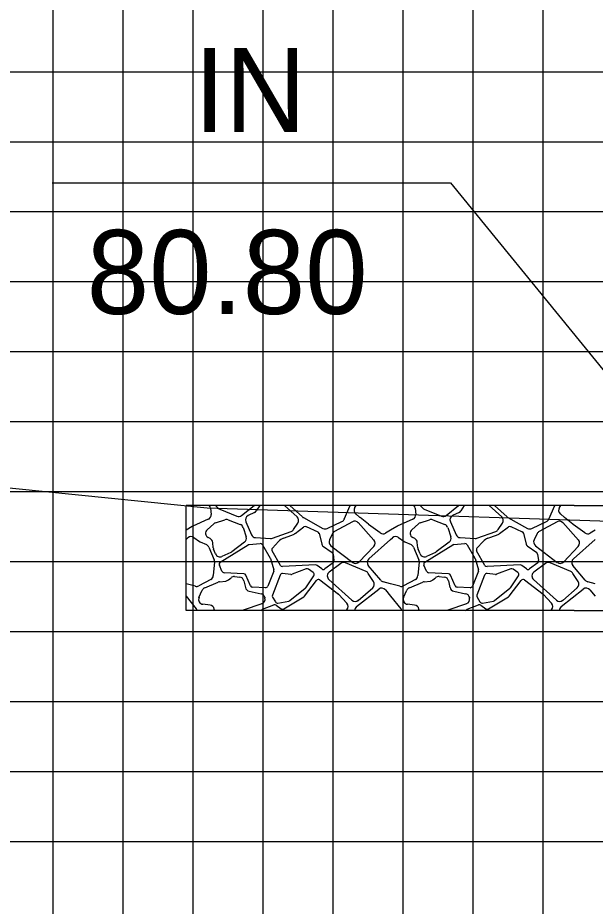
# Model space of a CAD drawing. Extents: x 857504 to 857847, y 364765 to 364985.
# Drawn here: x 857586.8 to 857595.05, y 364923.38 to 364936.07 of the extents above; entities that cross this region are included whole.
import ezdxf

# ---------------------------------------------------------------- set-up
doc = ezdxf.new("R2010")
doc.units = 0
for name, color, linetype in [('ANNOTATION', 7, 'Continuous'), ('D_Roadway_SlopeLines', 7, 'Continuous'), ('MAJOR', 7, 'Continuous'), ('MINOR', 7, 'Continuous'), ('S_Roadway_Centerline', 7, 'Continuous')]:
    doc.layers.add(name, color=color, linetype=linetype)

msp = doc.modelspace()

# ---------------------------------------------------------------- linework, layer by layer
at = {"layer": 'ANNOTATION'}
msp.add_lwpolyline([(857587.292, 364933.714), (857592.983, 364933.714), (857596.751, 364929.101)], dxfattribs=at)
at = {"layer": 'D_Roadway_SlopeLines'}
for p, q in [((857594.751, 364929.101), (857589.205, 364929.101)), ((857589.555, 364929.066), (857589.564, 364928.975)), ((857589.628, 364929.101), (857589.664, 364929.064)), ((857589.687, 364929.049), (857589.931, 364928.949)), ((857590, 364928.959), (857590.178, 364929.101)), ((857590.259, 364929.101), (857590.209, 364929.028)), ((857590.792, 364928.943), (857590.611, 364929.101)), ((857590.688, 364929.101), (857590.87, 364928.939)), ((857591.467, 364928.909), (857591.55, 364929.101)), ((857591.62, 364929.077), (857591.638, 364929.101)), ((857592.48, 364929.066), (857592.488, 364928.975)), ((857592.552, 364929.101), (857592.589, 364929.064)), ((857592.611, 364929.049), (857592.856, 364928.949)), ((857592.925, 364928.959), (857593.102, 364929.101)), ((857593.183, 364929.101), (857593.134, 364929.028)), ((857593.717, 364928.943), (857593.536, 364929.101)), ((857593.613, 364929.101), (857593.794, 364928.939)), ((857594.392, 364928.909), (857594.475, 364929.101)), ((857594.545, 364929.077), (857594.563, 364929.101)), ((857594.751, 364929.101), (857596.751, 364929.101)), ((857589.523, 364928.906), (857589.3, 364928.807)), ((857589.626, 364928.855), (857589.76, 364928.899)), ((857589.806, 364928.898), (857589.98, 364928.832)), ((857590.183, 364929.005), (857590.091, 364928.959)), ((857590.882, 364928.93), (857591.162, 364928.776)), ((857591.691, 364928.934), (857591.631, 364928.982)), ((857591.811, 364928.836), (857591.692, 364928.933)), ((857592.448, 364928.906), (857592.224, 364928.807)), ((857592.551, 364928.855), (857592.685, 364928.899)), ((857592.731, 364928.898), (857592.905, 364928.832)), ((857593.108, 364929.005), (857593.016, 364928.959)), ((857593.807, 364928.93), (857594.087, 364928.776)), ((857594.616, 364928.934), (857594.556, 364928.982)), ((857594.736, 364928.836), (857594.617, 364928.933)), ((857589.293, 364928.803), (857589.205, 364928.751)), ((857589.507, 364928.757), (857589.603, 364928.841)), ((857590.02, 364928.79), (857590.066, 364928.655)), ((857590.059, 364928.87), (857590.141, 364928.685)), ((857590.741, 364928.759), (857590.804, 364928.853)), ((857590.763, 364928.702), (857590.89, 364928.797)), ((857590.924, 364928.801), (857591.087, 364928.729)), ((857591.224, 364928.775), (857591.434, 364928.874)), ((857591.584, 364928.872), (857591.329, 364928.732)), ((857591.889, 364928.61), (857591.667, 364928.858)), ((857591.98, 364928.711), (857591.814, 364928.834)), ((857592.217, 364928.803), (857592.13, 364928.751)), ((857592.432, 364928.757), (857592.528, 364928.841)), ((857592.945, 364928.79), (857592.991, 364928.655)), ((857592.984, 364928.87), (857593.065, 364928.685)), ((857593.665, 364928.759), (857593.729, 364928.853)), ((857593.687, 364928.702), (857593.814, 364928.797)), ((857593.849, 364928.801), (857594.012, 364928.729)), ((857594.149, 364928.775), (857594.359, 364928.874)), ((857594.508, 364928.872), (857594.253, 364928.732)), ((857594.814, 364928.61), (857594.592, 364928.858)), ((857594.905, 364928.711), (857594.739, 364928.834)), ((857589.205, 364928.617), (857589.233, 364928.641)), ((857589.317, 364928.645), (857589.396, 364928.59)), ((857589.55, 364928.63), (857589.52, 364928.645)), ((857590.199, 364928.644), (857590.412, 364928.632)), ((857590.439, 364928.636), (857590.707, 364928.733)), ((857590.597, 364928.636), (857590.716, 364928.677)), ((857591.106, 364928.706), (857591.145, 364928.549)), ((857591.3, 364928.703), (857591.256, 364928.614)), ((857592.13, 364928.751), (857592.056, 364928.707)), ((857592.13, 364928.617), (857592.157, 364928.641)), ((857592.242, 364928.645), (857592.321, 364928.59)), ((857592.475, 364928.63), (857592.445, 364928.645)), ((857593.124, 364928.644), (857593.337, 364928.632)), ((857593.364, 364928.636), (857593.632, 364928.733)), ((857593.521, 364928.636), (857593.641, 364928.677)), ((857594.031, 364928.706), (857594.069, 364928.549)), ((857594.225, 364928.703), (857594.181, 364928.614)), ((857595.054, 364928.751), (857594.98, 364928.707)), ((857589.408, 364928.583), (857589.497, 364928.544)), ((857589.533, 364928.508), (857589.607, 364928.329)), ((857589.594, 364928.499), (857589.587, 364928.575)), ((857589.695, 364928.295), (857590.094, 364928.54)), ((857590.042, 364928.579), (857589.858, 364928.439)), ((857590.109, 364928.545), (857590.265, 364928.558)), ((857590.297, 364928.541), (857590.409, 364928.351)), ((857590.439, 364928.495), (857590.527, 364928.59)), ((857591.158, 364928.529), (857591.293, 364928.43)), ((857591.276, 364928.529), (857591.588, 364928.291)), ((857591.679, 364928.298), (857591.888, 364928.518)), ((857591.817, 364928.343), (857592.13, 364928.617)), ((857592.333, 364928.583), (857592.422, 364928.544)), ((857592.458, 364928.508), (857592.532, 364928.329)), ((857592.518, 364928.499), (857592.511, 364928.575)), ((857592.62, 364928.295), (857593.019, 364928.54)), ((857592.967, 364928.579), (857592.782, 364928.439)), ((857593.034, 364928.545), (857593.189, 364928.558)), ((857593.222, 364928.541), (857593.333, 364928.351)), ((857593.364, 364928.495), (857593.452, 364928.59)), ((857594.082, 364928.529), (857594.218, 364928.43)), ((857594.2, 364928.529), (857594.512, 364928.291)), ((857594.603, 364928.298), (857594.812, 364928.518)), ((857594.742, 364928.343), (857595.054, 364928.617)), ((857589.628, 364928.411), (857589.599, 364928.478)), ((857589.844, 364928.432), (857589.718, 364928.376)), ((857590.553, 364928.247), (857590.434, 364928.455)), ((857591.306, 364928.408), (857591.32, 364928.319)), ((857592.552, 364928.411), (857592.524, 364928.478)), ((857592.769, 364928.432), (857592.643, 364928.376)), ((857593.478, 364928.247), (857593.359, 364928.455)), ((857594.231, 364928.408), (857594.245, 364928.319)), ((857589.612, 364928.297), (857589.594, 364928.101)), ((857589.719, 364928.164), (857589.681, 364928.253)), ((857590.412, 364928.344), (857590.46, 364928.185)), ((857591.057, 364928.255), (857590.585, 364928.23)), ((857591.307, 364928.286), (857591.189, 364928.196)), ((857591.418, 364928.275), (857591.252, 364928.152)), ((857591.78, 364928.159), (857591.486, 364928.283)), ((857592.537, 364928.297), (857592.519, 364928.101)), ((857592.643, 364928.164), (857592.606, 364928.253)), ((857593.337, 364928.344), (857593.385, 364928.185)), ((857593.982, 364928.255), (857593.509, 364928.23)), ((857594.232, 364928.286), (857594.114, 364928.196)), ((857594.343, 364928.275), (857594.177, 364928.152)), ((857594.704, 364928.159), (857594.411, 364928.283)), ((857590.031, 364928.126), (857589.748, 364928.143)), ((857590.459, 364928.163), (857590.374, 364927.951)), ((857590.705, 364928.118), (857590.584, 364928.13)), ((857590.923, 364928.196), (857590.72, 364928.12)), ((857591.021, 364928.148), (857590.954, 364928.192)), ((857591.147, 364928.196), (857591.08, 364928.248)), ((857591.988, 364928.036), (857591.81, 364928.247)), ((857591.885, 364928.018), (857591.81, 364928.133)), ((857592.956, 364928.126), (857592.673, 364928.143)), ((857593.384, 364928.163), (857593.299, 364927.951)), ((857593.63, 364928.118), (857593.509, 364928.13)), ((857593.848, 364928.196), (857593.645, 364928.12)), ((857593.946, 364928.148), (857593.879, 364928.192)), ((857594.072, 364928.196), (857594.005, 364928.248)), ((857594.912, 364928.036), (857594.735, 364928.247)), ((857594.81, 364928.018), (857594.735, 364928.133)), ((857589.558, 364928.047), (857589.388, 364927.956)), ((857589.472, 364927.928), (857589.665, 364928.008)), ((857589.683, 364928.013), (857589.775, 364928.024)), ((857589.81, 364928.04), (857589.848, 364928.072)), ((857589.899, 364928.088), (857589.972, 364928.081)), ((857590.032, 364928.027), (857590.054, 364927.93)), ((857590.126, 364927.956), (857590.06, 364928.106)), ((857590.549, 364928.108), (857590.439, 364927.823)), ((857590.898, 364927.809), (857591.07, 364928.033)), ((857590.916, 364927.929), (857591.03, 364928.1)), ((857591.118, 364928.04), (857591.384, 364927.836)), ((857591.247, 364928.046), (857591.576, 364927.749)), ((857592.13, 364927.985), (857592.023, 364928.014)), ((857592.483, 364928.047), (857592.312, 364927.956)), ((857592.397, 364927.928), (857592.59, 364928.008)), ((857592.608, 364928.013), (857592.699, 364928.024)), ((857592.735, 364928.04), (857592.773, 364928.072)), ((857592.824, 364928.088), (857592.897, 364928.081)), ((857592.957, 364928.027), (857592.978, 364927.93)), ((857593.051, 364927.956), (857592.985, 364928.106)), ((857593.473, 364928.108), (857593.364, 364927.823)), ((857593.823, 364927.809), (857593.995, 364928.033)), ((857593.841, 364927.929), (857593.955, 364928.1)), ((857594.043, 364928.04), (857594.309, 364927.836)), ((857594.172, 364928.046), (857594.501, 364927.749)), ((857595.054, 364927.985), (857594.947, 364928.014)), ((857589.338, 364927.95), (857589.205, 364927.985)), ((857589.39, 364927.787), (857589.436, 364927.892)), ((857590.107, 364927.878), (857590.277, 364927.843)), ((857590.341, 364927.929), (857590.156, 364927.935)), ((857590.69, 364927.745), (857590.909, 364927.921)), ((857591.644, 364927.658), (857591.959, 364927.907)), ((857591.667, 364927.748), (857591.873, 364927.929)), ((857592.054, 364927.897), (857592.13, 364927.806)), ((857592.263, 364927.95), (857592.13, 364927.985)), ((857592.315, 364927.787), (857592.361, 364927.892)), ((857593.031, 364927.878), (857593.202, 364927.843)), ((857593.266, 364927.929), (857593.081, 364927.935)), ((857593.614, 364927.745), (857593.834, 364927.921)), ((857594.568, 364927.658), (857594.884, 364927.907)), ((857594.591, 364927.748), (857594.797, 364927.929)), ((857594.979, 364927.897), (857595.054, 364927.806)), ((857589.205, 364927.806), (857589.351, 364927.628)), ((857590.33, 364927.791), (857590.333, 364927.78)), ((857590.442, 364927.793), (857590.482, 364927.726)), ((857590.604, 364927.627), (857590.889, 364927.8)), ((857591.389, 364927.832), (857591.504, 364927.707)), ((857592.13, 364927.806), (857592.276, 364927.628)), ((857593.255, 364927.791), (857593.257, 364927.78)), ((857593.366, 364927.793), (857593.406, 364927.726)), ((857593.528, 364927.627), (857593.814, 364927.8)), ((857594.313, 364927.832), (857594.429, 364927.707)), ((857589.548, 364927.681), (857589.446, 364927.692)), ((857589.609, 364927.616), (857589.609, 364927.621)), ((857590.289, 364927.7), (857590.021, 364927.606)), ((857590.299, 364927.621), (857590.461, 364927.684)), ((857590.494, 364927.68), (857590.566, 364927.628)), ((857590.517, 364927.71), (857590.674, 364927.738)), ((857592.473, 364927.681), (857592.37, 364927.692)), ((857592.534, 364927.616), (857592.533, 364927.621)), ((857593.213, 364927.7), (857592.946, 364927.606)), ((857593.224, 364927.621), (857593.386, 364927.684)), ((857593.418, 364927.68), (857593.491, 364927.628)), ((857593.442, 364927.71), (857593.599, 364927.738)), ((857590.274, 364927.601), (857590.289, 364927.614)), ((857591.504, 364927.614), (857591.491, 364927.601)), ((857593.199, 364927.601), (857593.214, 364927.614)), ((857594.428, 364927.614), (857594.416, 364927.601)), ((857594.751, 364927.601), (857596.751, 364927.601))]:
    msp.add_line(p, q, dxfattribs=at)
msp.add_lwpolyline([(857594.751, 364927.601), (857589.205, 364927.601), (857589.205, 364929.101)], dxfattribs=at)
for centre, radius, start, end in [((857589.487, 364929.06), 0.0684, 5.1944, 36.5817), ((857589.713, 364929.112), 0.0684, 225, 247.6938), ((857590.153, 364929.066), 0.0684, 296.5651, 325.7843), ((857591.674, 364929.035), 0.0684, 141.953, 231.3402), ((857592.412, 364929.06), 0.0684, 5.1944, 36.5817), ((857592.637, 364929.112), 0.0684, 225, 247.6938), ((857593.077, 364929.066), 0.0684, 296.5651, 325.7843), ((857594.599, 364929.035), 0.0684, 141.953, 231.3402), ((857589.496, 364928.969), 0.0684, 293.9625, 5.1944), ((857589.782, 364928.834), 0.0684, 69.0265, 108.4349), ((857589.957, 364929.012), 0.0684, 247.6938, 308.6598), ((857590.122, 364928.898), 0.0684, 116.5651, 203.7495), ((857590.747, 364928.891), 0.0684, 326.0035, 48.8937), ((857590.915, 364928.99), 0.0684, 228.2412, 241.294), ((857591.405, 364928.936), 0.0684, 295.4039, 336.6444), ((857591.649, 364928.88), 0.0684, 50.9061, 51.3402), ((857592.42, 364928.969), 0.0684, 293.9625, 5.1944), ((857592.707, 364928.834), 0.0684, 69.0265, 108.4349), ((857592.882, 364929.012), 0.0684, 247.6938, 308.6598), ((857593.046, 364928.898), 0.0684, 116.5651, 203.7495), ((857593.672, 364928.891), 0.0684, 326.0035, 48.8937), ((857593.84, 364928.99), 0.0684, 228.2412, 241.294), ((857594.329, 364928.936), 0.0684, 295.4039, 336.6444), ((857594.573, 364928.88), 0.0684, 50.9061, 51.3402), ((857589.327, 364928.744), 0.0684, 113.9625, 120.6507), ((857589.648, 364928.79), 0.0684, 108.4349, 131.1859), ((857589.956, 364928.768), 0.0684, 18.7413, 69.0265), ((857590.684, 364928.797), 0.0684, 289.9256, 326.0035), ((857590.91, 364928.769), 0.0342, 66.1398, 126.7644), ((857591.195, 364928.836), 0.0684, 241.294, 295.4039), ((857591.616, 364928.812), 0.0684, 41.8334, 118.7575), ((857591.855, 364928.889), 0.0684, 230.9061, 233.4711), ((857592.252, 364928.744), 0.0684, 113.9625, 120.6507), ((857592.573, 364928.79), 0.0684, 108.4349, 131.1859), ((857592.88, 364928.768), 0.0684, 18.7413, 69.0265), ((857593.609, 364928.797), 0.0684, 289.9256, 326.0035), ((857593.835, 364928.769), 0.0342, 66.1398, 126.7644), ((857594.12, 364928.836), 0.0684, 241.294, 295.4039), ((857594.541, 364928.812), 0.0684, 41.8334, 118.7575), ((857594.779, 364928.889), 0.0684, 230.9061, 233.4711), ((857589.278, 364928.59), 0.0684, 54.7824, 131.257), ((857589.552, 364928.706), 0.0684, 131.1859, 242.3005), ((857590.001, 364928.633), 0.0684, 307.0199, 18.7413), ((857590.203, 364928.712), 0.0684, 203.7495, 266.7755), ((857590.416, 364928.7), 0.0684, 266.7755, 289.9256), ((857590.653, 364928.474), 0.171, 109.1336, 137.3215), ((857590.66, 364928.839), 0.171, 289.1336, 306.7644), ((857591.073, 364928.697), 0.0342, 13.7608, 66.1398), ((857591.361, 364928.672), 0.0684, 118.7575, 153.4931), ((857592.021, 364928.766), 0.0684, 233.4711, 300.6507), ((857592.203, 364928.59), 0.0684, 54.7824, 131.257), ((857592.477, 364928.706), 0.0684, 131.1859, 242.3005), ((857592.926, 364928.633), 0.0684, 307.0199, 18.7413), ((857593.128, 364928.712), 0.0684, 203.7495, 266.7755), ((857593.34, 364928.7), 0.0684, 266.7755, 289.9256), ((857593.577, 364928.474), 0.171, 109.1336, 137.3215), ((857593.585, 364928.839), 0.171, 289.1336, 306.7644), ((857593.998, 364928.697), 0.0342, 13.7608, 66.1398), ((857594.286, 364928.672), 0.0684, 118.7575, 153.4931), ((857594.946, 364928.766), 0.0684, 233.4711, 300.6507), ((857589.436, 364928.646), 0.0684, 234.7824, 246.3706), ((857589.47, 364928.481), 0.0684, 22.4794, 66.3706), ((857589.518, 364928.569), 0.0684, 5.1944, 62.3005), ((857590.112, 364928.511), 0.0342, 94.6669, 121.5514), ((857590.267, 364928.524), 0.0342, 30.5102, 94.6669), ((857591.178, 364928.557), 0.0342, 193.7608, 233.6864), ((857591.317, 364928.583), 0.0684, 153.4931, 232.6367), ((857591.838, 364928.565), 0.0684, 316.4321, 41.8334), ((857592.36, 364928.646), 0.0684, 234.7824, 246.3706), ((857592.395, 364928.481), 0.0684, 22.4794, 66.3706), ((857592.443, 364928.569), 0.0684, 5.1944, 62.3005), ((857593.036, 364928.511), 0.0342, 94.6669, 121.5514), ((857593.192, 364928.524), 0.0342, 30.5102, 94.6669), ((857594.102, 364928.557), 0.0342, 193.7608, 233.6864), ((857594.242, 364928.583), 0.0684, 153.4931, 232.6367), ((857594.763, 364928.565), 0.0684, 316.4321, 41.8334), ((857589.662, 364928.505), 0.0684, 185.1944, 203.3852), ((857589.69, 364928.438), 0.0684, 203.3852, 293.8602), ((857589.817, 364928.494), 0.0684, 293.8602, 307.0199), ((857590.464, 364928.472), 0.0342, 137.3215, 209.792), ((857591.273, 364928.402), 0.0342, 8.7462, 53.6864), ((857592.586, 364928.505), 0.0684, 185.1944, 203.3852), ((857592.615, 364928.438), 0.0684, 203.3852, 293.8602), ((857592.741, 364928.494), 0.0684, 293.8602, 307.0199), ((857593.389, 364928.472), 0.0342, 137.3215, 209.792), ((857594.197, 364928.402), 0.0342, 8.7462, 53.6864), ((857589.544, 364928.303), 0.0684, 354.8056, 22.4794), ((857589.713, 364928.266), 0.0342, 121.5514, 202.6199), ((857590.379, 364928.334), 0.0342, 16.9275, 30.5102), ((857591.059, 364928.22), 0.0342, 52.4314, 92.9903), ((857591.286, 364928.313), 0.0342, 307.5348, 8.7462), ((857591.459, 364928.22), 0.0684, 66.9778, 126.6071), ((857591.629, 364928.345), 0.0684, 232.6367, 316.4321), ((857591.863, 364928.291), 0.0684, 131.257, 219.9575), ((857592.468, 364928.303), 0.0684, 354.8056, 22.4794), ((857592.638, 364928.266), 0.0342, 121.5514, 202.6199), ((857593.304, 364928.334), 0.0342, 16.9275, 30.5102), ((857593.984, 364928.22), 0.0342, 52.4314, 92.9903), ((857594.211, 364928.313), 0.0342, 307.5348, 8.7462), ((857594.384, 364928.22), 0.0684, 66.9778, 126.6071), ((857594.554, 364928.345), 0.0684, 232.6367, 316.4321), ((857594.787, 364928.291), 0.0684, 131.257, 219.9575), ((857589.75, 364928.177), 0.0342, 202.6199, 266.6726), ((857590.029, 364928.092), 0.0342, 23.7495, 86.6726), ((857590.427, 364928.176), 0.0342, 338.1986, 16.9275), ((857590.581, 364928.096), 0.0342, 84.4278, 159.0071), ((857590.583, 364928.264), 0.0342, 209.792, 272.9903), ((857590.935, 364928.164), 0.0342, 56.3099, 110.4835), ((857591.002, 364928.119), 0.0342, 326.3099, 56.3099), ((857591.168, 364928.223), 0.0342, 232.4314, 307.5348), ((857591.293, 364928.097), 0.0684, 126.6071, 227.8776), ((857591.753, 364928.096), 0.0684, 32.9625, 66.9778), ((857592.675, 364928.177), 0.0342, 202.6199, 266.6726), ((857592.954, 364928.092), 0.0342, 23.7495, 86.6726), ((857593.352, 364928.176), 0.0342, 338.1986, 16.9275), ((857593.505, 364928.096), 0.0342, 84.4278, 159.0071), ((857593.508, 364928.264), 0.0342, 209.792, 272.9903), ((857593.86, 364928.164), 0.0342, 56.3099, 110.4835), ((857593.927, 364928.119), 0.0342, 326.3099, 56.3099), ((857594.093, 364928.223), 0.0342, 232.4314, 307.5348), ((857594.218, 364928.097), 0.0684, 126.6071, 227.8776), ((857594.678, 364928.096), 0.0684, 32.9625, 66.9778), ((857589.526, 364928.107), 0.0684, 298.0725, 354.8056), ((857589.692, 364927.945), 0.0684, 97.125, 112.6199), ((857589.766, 364928.092), 0.0684, 277.125, 310.3645), ((857589.892, 364928.02), 0.0684, 84.2894, 130.3645), ((857589.965, 364928.013), 0.0684, 12.4074, 84.2894), ((857590.708, 364928.152), 0.0342, 264.4278, 290.4835), ((857591.097, 364928.013), 0.0342, 52.5946, 142.5946), ((857591.828, 364927.98), 0.0684, 311.2462, 32.9625), ((857592.04, 364928.08), 0.0684, 219.9575, 255.2564), ((857592.451, 364928.107), 0.0684, 298.0725, 354.8056), ((857592.616, 364927.945), 0.0684, 97.125, 112.6199), ((857592.691, 364928.092), 0.0684, 277.125, 310.3645), ((857592.817, 364928.02), 0.0684, 84.2894, 130.3645), ((857592.89, 364928.013), 0.0684, 12.4074, 84.2894), ((857593.633, 364928.152), 0.0342, 264.4278, 290.4835), ((857594.022, 364928.013), 0.0342, 52.5946, 142.5946), ((857594.752, 364927.98), 0.0684, 311.2462, 32.9625), ((857594.965, 364928.08), 0.0684, 219.9575, 255.2564), ((857589.355, 364928.016), 0.0684, 255.2564, 298.0725), ((857589.499, 364927.864), 0.0684, 112.6199, 156.3179), ((857590.12, 364927.945), 0.0684, 192.4074, 258.3664), ((857590.157, 364927.969), 0.0342, 203.7495, 268.1221), ((857590.343, 364927.963), 0.0342, 268.1221, 338.1986), ((857590.888, 364927.948), 0.0342, 308.7742, 326.3099), ((857592.002, 364927.854), 0.0684, 39.4712, 128.373), ((857592.28, 364928.016), 0.0684, 255.2564, 298.0725), ((857592.423, 364927.864), 0.0684, 112.6199, 156.3179), ((857593.045, 364927.945), 0.0684, 192.4074, 258.3664), ((857593.082, 364927.969), 0.0342, 203.7495, 268.1221), ((857593.267, 364927.963), 0.0342, 268.1221, 338.1986), ((857593.812, 364927.948), 0.0342, 308.7742, 326.3099), ((857594.926, 364927.854), 0.0684, 39.4712, 128.373), ((857589.453, 364927.76), 0.0684, 156.3179, 263.9458), ((857590.263, 364927.776), 0.0684, 13.134, 78.3664), ((857590.266, 364927.765), 0.0684, 289.406, 13.134), ((857590.471, 364927.811), 0.0342, 159.0071, 210.6507), ((857590.668, 364927.772), 0.0342, 280.204, 308.7742), ((857590.871, 364927.83), 0.0342, 301.373, 322.5946), ((857591.364, 364927.809), 0.0342, 42.7891, 52.5946), ((857591.622, 364927.8), 0.0684, 227.8776, 311.2462), ((857592.378, 364927.76), 0.0684, 156.3179, 263.9458), ((857593.188, 364927.776), 0.0684, 13.134, 78.3664), ((857593.191, 364927.765), 0.0684, 289.406, 13.134), ((857593.396, 364927.811), 0.0342, 159.0071, 210.6507), ((857593.593, 364927.772), 0.0342, 280.204, 308.7742), ((857593.796, 364927.83), 0.0342, 301.373, 322.5946), ((857594.288, 364927.809), 0.0342, 42.7891, 52.5946), ((857594.546, 364927.8), 0.0684, 227.8776, 311.2462), ((857589.298, 364927.585), 0.0684, 13.3808, 39.4712), ((857589.541, 364927.613), 0.0684, 6.8428, 83.9458), ((857589.677, 364927.624), 0.0684, 186.8428, 200.3546), ((857590.312, 364927.589), 0.0342, 111.1941, 132.2073), ((857590.474, 364927.652), 0.0342, 54.4623, 111.1941), ((857590.511, 364927.743), 0.0342, 210.6507, 280.204), ((857590.586, 364927.656), 0.0342, 234.4623, 301.373), ((857591.454, 364927.661), 0.0684, 316.3639, 42.7891), ((857591.686, 364927.604), 0.0684, 128.373, 182.6858), ((857592.223, 364927.585), 0.0684, 13.3808, 39.4712), ((857592.465, 364927.613), 0.0684, 6.8428, 83.9458), ((857592.602, 364927.624), 0.0684, 186.8428, 200.3546), ((857593.237, 364927.589), 0.0342, 111.1941, 132.2073), ((857593.399, 364927.652), 0.0342, 54.4623, 111.1941), ((857593.436, 364927.743), 0.0342, 210.6507, 280.204), ((857593.511, 364927.656), 0.0342, 234.4623, 301.373), ((857594.379, 364927.661), 0.0684, 316.3639, 42.7891), ((857594.611, 364927.604), 0.0684, 128.373, 182.6858), ((857590.044, 364927.542), 0.0684, 109.406, 120.1633), ((857592.969, 364927.542), 0.0684, 109.406, 120.1633)]:
    msp.add_arc(centre, radius, start, end, dxfattribs=at)
at = {"layer": 'MAJOR'}
for p, q in [((857589.308, 364918.302), (857589.308, 364963.302)), ((857529.308, 364933.302), (857809.308, 364933.302)), ((857529.308, 364928.302), (857809.308, 364928.302))]:
    msp.add_line(p, q, dxfattribs=at)
at = {"layer": 'MINOR'}
for p, q in [((857587.308, 364918.302), (857587.308, 364963.302)), ((857588.308, 364918.302), (857588.308, 364963.302)), ((857590.308, 364918.302), (857590.308, 364963.302)), ((857591.308, 364918.302), (857591.308, 364963.302)), ((857592.308, 364918.302), (857592.308, 364963.302)), ((857593.308, 364918.302), (857593.308, 364963.302)), ((857594.308, 364918.302), (857594.308, 364963.302)), ((857529.308, 364935.302), (857809.308, 364935.302)), ((857529.308, 364934.302), (857809.308, 364934.302)), ((857529.308, 364932.302), (857809.308, 364932.302)), ((857529.308, 364931.302), (857809.308, 364931.302)), ((857529.308, 364930.302), (857809.308, 364930.302)), ((857529.308, 364929.302), (857809.308, 364929.302)), ((857529.308, 364927.302), (857809.308, 364927.302)), ((857529.308, 364926.302), (857809.308, 364926.302)), ((857529.308, 364925.302), (857809.308, 364925.302)), ((857529.308, 364924.302), (857809.308, 364924.302))]:
    msp.add_line(p, q, dxfattribs=at)
at = {"layer": 'S_Roadway_Centerline'}
msp.add_lwpolyline([(857584.882, 364929.536), (857589.507, 364929.07), (857605.051, 364928.554), (857609.686, 364929.009), (857617.872, 364928.847), (857628.738, 364929.223), (857633.626, 364929.027), (857649.334, 364929.348), (857650.574, 364929.405), (857652.569, 364929.374), (857670.927, 364928.662), (857671.927, 364928.328), (857675.678, 364928.298), (857686.579, 364928.089), (857691.116, 364927.904), (857696.293, 364927.189), (857700.009, 364926.224), (857705.06, 364925.841), (857708.975, 364925.446), (857711.586, 364925.335), (857713.504, 364924.853), (857714.175, 364924.733), (857714.491, 364924.707), (857723.7, 364923.452)], dxfattribs=at)

# ---------------------------------------------------------------- texts
at = {"layer": 'ANNOTATION'}
for s, p in [('IN', (857589.319, 364934.44)), ('80.80', (857587.785, 364931.84))]:
    msp.add_text(s, height=1.2, dxfattribs=at).set_placement(p)

doc.saveas('drawing.dxf')
